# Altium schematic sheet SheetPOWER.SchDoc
size A4
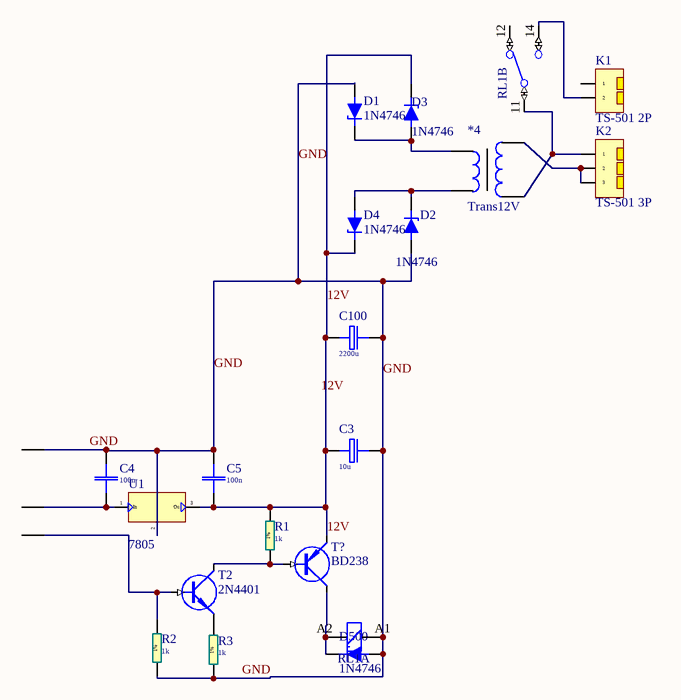
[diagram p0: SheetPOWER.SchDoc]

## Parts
1  FAT_single_BLC_pin  [Single_BLC_fat_Pin]  (value not drawn)
2  FAT_single_BLC_pin  [Single_BLC_fat_Pin]  (value not drawn)
3  FAT_single_BLC_pin  [Single_BLC_fat_Pin]  (value not drawn)
*4  Trans12V  [Trans_12V]
C3  10u  [El-d5-h11-F2.54]
C4  100n  [C1206(3216)]
C5  100n  [C1206(3216)]
C100  2200u  [El-d13-h21-F5.08]
D1  1N4746  [DO-41-300]
D2  1N4746  [DO-41-300]
D3  1N4746  [DO-41-300]
D4  1N4746  [DO-41-300]
D500  1N4746  [DO-41-300]
K1  TS-501 2P  [TS-501 2P-2.5]
K2  TS-501 3P  [TS-501 3P-2.5]
R1  1k  [R1206]
R2  1k  [R1206]
R3  1k  [R1206]
RL1  REL_TYCO_SCHRACK_RT31xxxx  [REL_TYCO_SCHRACK_RT31XXXX]  (value not drawn)  (parts A,B of 2)
T2  2N4401  [TO92C1]
T?  BD238  [TO126-10]
U1  7805  [TO220-1A 2.54]

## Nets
12V: C3.1 C5.1 C100.1 D3.2(C) D4.2(C) R1.2 T?.1(E) U1.3(Ou)
GND: 1.0(BLC_pin) C3.2 C4.2 C5.2 C100.2 D1.1(A) D2.1(A) D500.1(A) R2.1 R3.1 RL1.A1 U1.2(G)
Net2_0: 2.0(BLC_pin) C4.1 U1.1(In)
Net3_0: 3.0(BLC_pin) R2.2 T2.2(B)
Net*4_1: *4.1 K2.1 RL1.11(C)
Net*4_2: *4.2 K2.2 K2.3
Net*4_3: *4.3 D1.2(C) D3.1(A)
Net*4_4: *4.4 D2.2(C) D4.1(A)
NetD500_2: D500.2(C) RL1.A2 T?.2(C)
NetK1_2: K1.2 RL1.14(NO)
NetR1_1: R1.1 T2.1(C) T?.3(B)
NetR3_2: R3.2 T2.3(E)

Not connected (* = marked no-connect by the designer): K1 1; RL1 12(NC)

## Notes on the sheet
- Labels drawn without touching a wire or pin: 12V

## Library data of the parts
C3 = 10u-35V: 35V
C4 C5 = C_1206: SMD-0805 50V Y5V +80/-20%
C100 = 2200u-16V 105F: 16V 105C 39m 1.9A
D1-D4 D500 = 1N4746: 18V 1W
K1 = TS-501 2P: 10A/300V AC 5mm
K2 = TS-501 3P: 10A/300V AC 5mm
R1-R3 = R-1206-1%: SMD 1206 0.125W 1% 200V
RL1 = REL_TYCO_SCHRACK_RT314012: RT PCB Relay Form C (1 CO Contact)
T2 = 2N4401: 40V 0.6A 250MHz 6.5pF (5V)
T? = BD238: 80V 2A 3MHz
